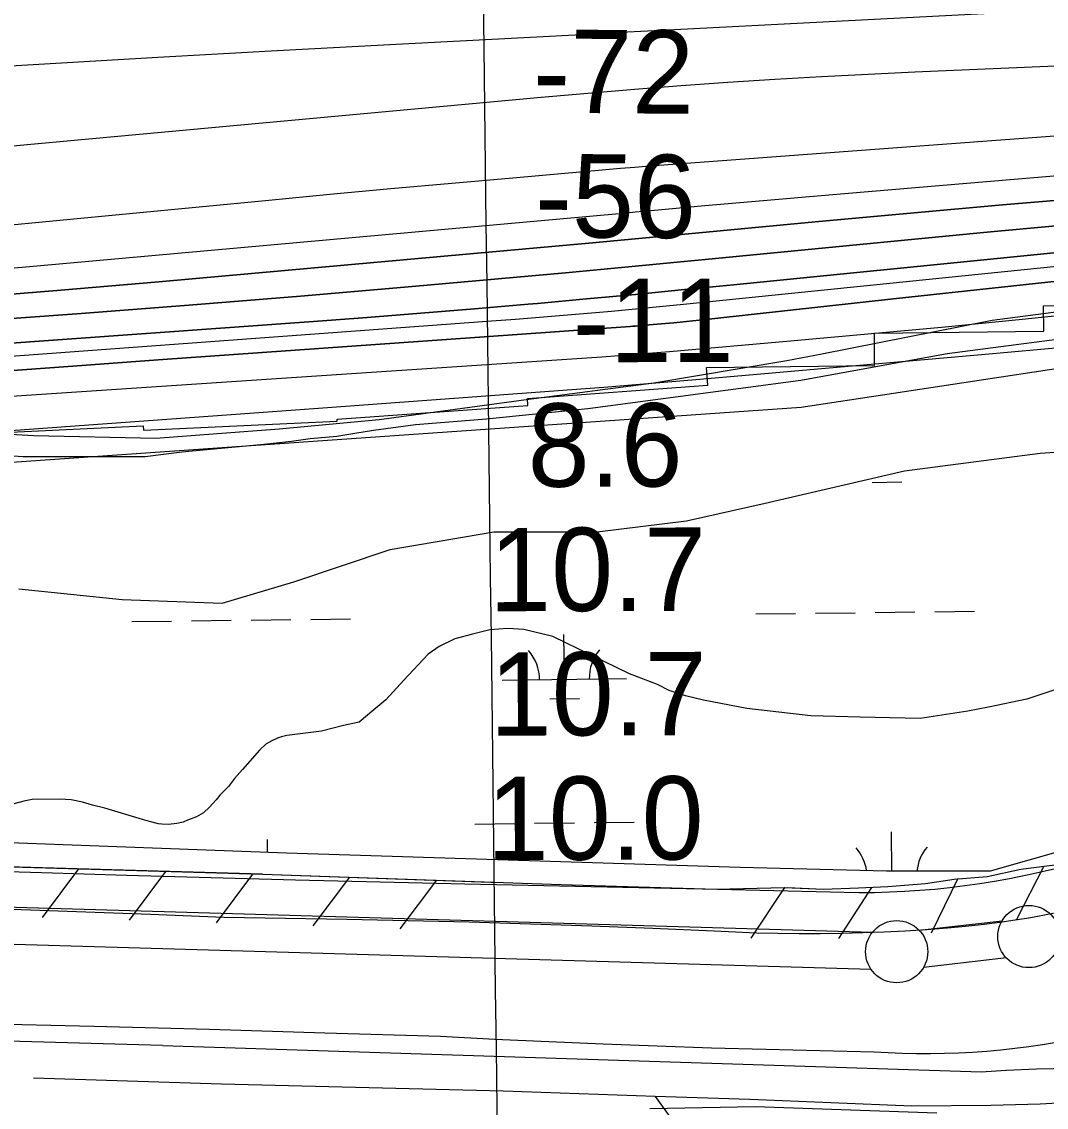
# Model space of a CAD drawing. Extents: x 3704301 to 3742427, y 506229 to 532009.
# Drawn here: x 3718668 to 3719492, y 518448 to 519321 of the extents above; entities that cross this region are included whole.
import ezdxf

# ---------------------------------------------------------------- set-up
doc = ezdxf.new("R2010")
doc.units = 0
for name, color, linetype in [('V-FLOD-BASE', 7, 'Continuous'), ('V-GRID-MAJR', 7, 'Continuous'), ('V-LEVE-TOET', 7, 'Continuous'), ('V-RIVR-EDGE', 7, 'Continuous'), ('V-RIVR-RANG', 7, 'Continuous'), ('V-ROAD-CNTR', 7, 'Continuous'), ('V-RRAP-FSHR', 7, 'Continuous'), ('V-RRAP-RVMT', 7, 'Continuous'), ('V-SITE-VEGE', 7, 'Continuous'), ('V-SURV-LINE', 7, 'Continuous'), ('V-TOPO-DPTH', 7, 'Continuous'), ('V-TOPO-MAJR', 7, 'Continuous'), ('V-TOPO-MINR', 7, 'Continuous'), ('V-TOPO-SHOR', 7, 'Continuous'), ('V-TOPO-WATR', 7, 'Continuous'), ('V-WETL-SWMP', 7, 'Continuous')]:
    doc.layers.add(name, color=color, linetype=linetype)

msp = doc.modelspace()

# ---------------------------------------------------------------- linework, layer by layer
at = {"layer": 'V-FLOD-BASE'}
msp.add_lwpolyline([(3719504.11, 518605.57), (3719491.77, 518603.07), (3719479.39, 518600.8), (3719466.96, 518598.76), (3719454.5, 518596.94), (3719442.02, 518595.35), (3719429.5, 518593.99), (3719412.49, 518592.48), (3719395.46, 518591.19), (3719378.42, 518590.11), (3719361.37, 518589.25), (3719344.31, 518588.6), (3719327.24, 518588.17), (3719310.16, 518587.95), (3719293.08, 518587.94), (3719276.01, 518588.15), (3719258.94, 518588.57), (3719241.88, 518589.21), (3719224.82, 518590.06), (3719175.59, 518592.16), (3719126.35, 518594.05), (3719077.1, 518595.73), (3719027.85, 518597.2), (3718978.58, 518598.46), (3718929.32, 518599.51), (3718880.05, 518600.35), (3718830.78, 518600.98), (3718771.41, 518603.39), (3718712.04, 518605.6), (3718652.66, 518607.61)], dxfattribs=at)
at = {"layer": 'V-GRID-MAJR'}
msp.add_spline([(3719130.79, 511775.21), (3719057.66, 517832.65), (3718984.49, 523893.16), (3718911.33, 529953.69), (3718911.29, 529956.76)], degree=3, dxfattribs=at)
at = {"layer": 'V-LEVE-TOET'}
for points in [[(3719505.13, 518641.52), (3719490.91, 518638.21), (3719476.65, 518635.12), (3719462.34, 518632.24), (3719450.38, 518630.05), (3719438.38, 518628.09), (3719426.34, 518626.37), (3719414.28, 518624.88), (3719402.18, 518623.63), (3719390.07, 518622.62), (3719377.94, 518621.84), (3719365.79, 518621.3), (3719353.64, 518621), (3719341.48, 518620.93), (3719329.32, 518621.11), (3719227.66, 518623.6), (3719125.99, 518625.82), (3719024.32, 518627.78), (3718956.25, 518629.32), (3718888.18, 518631), (3718820.11, 518632.82), (3718752.05, 518634.78), (3718683.99, 518636.88), (3718610.48, 518638.99)], [(3718633.06, 518515.85), (3718725.98, 518513.6), (3718818.88, 518511.13), (3718911.79, 518508.44), (3719004.68, 518505.54), (3719048.25, 518503.31), (3719091.83, 518501.27), (3719135.42, 518499.42), (3719179.01, 518497.77), (3719222.62, 518496.31), (3719266.22, 518495.05), (3719309.84, 518493.98), (3719353.46, 518493.11), (3719364.76, 518492.44), (3719376.08, 518491.98), (3719387.4, 518491.73), (3719398.72, 518491.7), (3719410.05, 518491.88), (3719421.36, 518492.27), (3719432.67, 518492.86), (3719443.97, 518493.67), (3719455.25, 518494.69), (3719466.51, 518495.92), (3719477.74, 518497.36), (3719488.94, 518499.01), (3719500.12, 518500.86)]]:
    msp.add_lwpolyline(points, dxfattribs=at)
at = {"layer": 'V-RIVR-EDGE'}
msp.add_lwpolyline([(3718613.12, 518992.21), (3718677.35, 518988.45), (3718775.8, 518986.4), (3718874.87, 518993.96), (3718955.33, 519001.57), (3719073.63, 519017.49), (3719176.32, 519031.04), (3719283.23, 519048.78), (3719311.45, 519054.12), (3719448.4, 519081.39), (3719507.85, 519089.05), (3719579.31, 519099.68), (3719683.19, 519106.03), (3719730.62, 519109.51), (3719758.24, 519110.04), (3719849.5, 519115.82), (3719962.37, 519120.95), (3720084.85, 519123.04), (3720165.91, 519129.45)], dxfattribs=at)
at = {"layer": 'V-ROAD-CNTR'}
for points in [[(3718780.98, 518498.22), (3718179.1, 518515.02), (3718151.75, 518517.62), (3718130.4, 518521.23), (3718088.05, 518529.99), (3717980.9, 518561.01), (3717958.85, 518565.95), (3717941.69, 518570.39), (3717923.51, 518575.15), (3717898.82, 518579.17), (3717869.02, 518585), (3717837.85, 518589.07), (3717807.08, 518590.8), (3717763.14, 518593.41), (3717074.31, 518630.34), (3717017.92, 518633.02), (3716960.94, 518633.92), (3716927.57, 518635.51), (3716890.7, 518634.15), (3716848.32, 518631.51), (3716792.89, 518627.14), (3716349.32, 518566.6)], [(3718780.98, 518498.22), (3719439.5, 518476.82), (3719459.76, 518478.2), (3719483.96, 518479.38), (3719497.61, 518479.51), (3719508.75, 518482.12), (3719520.69, 518484.95), (3719529.94, 518486.34), (3719540.83, 518488.96), (3719555.2, 518493.25), (3719641.91, 518528.4), (3719664.87, 518536.73), (3719678.8, 518542.61), (3719696, 518545.72), (3719715.73, 518546.86), (3719737.04, 518547.93), (3719767.36, 518551.18), (3719845.25, 518550.55), (3720856.93, 518524.63)]]:
    msp.add_lwpolyline(points, dxfattribs=at)
at = {"layer": 'V-RRAP-FSHR'}
for p, q in [((3719490, 518642.32), (3719467.61, 518598.93)), ((3718713.57, 518640.09), (3718684.41, 518600.92)), ((3718783.54, 518638.05), (3718754.38, 518598.88)), ((3718853.51, 518636.01), (3718824.35, 518596.84)), ((3718931.48, 518633.38), (3718902.12, 518594.36)), ((3719001.44, 518630.98), (3718972.08, 518591.96)), ((3719281.31, 518625.14), (3719254.24, 518584.5)), ((3719351.26, 518625.25), (3719324.69, 518584.28)), ((3719420.83, 518632.39), (3719399.36, 518588.53))]:
    msp.add_line(p, q, dxfattribs=at)
for points in [[(3713987.63, 518174.25), (3714448.77, 518564.74), (3714742.22, 518696.93), (3715881.89, 518753.27), (3716266.25, 518793.9), (3716843.09, 518890.74), (3717110.33, 518911.18), (3717741.27, 518924), (3718486.43, 518954.95), (3719294.78, 519011.25), (3719786.26, 519085.76), (3720431.33, 519110.59), (3720895.93, 519113.08), (3721218.47, 519068.37), (3721397.65, 519012.49), (3721721.32, 518965.44), (3721950.57, 518904.45), (3722606.87, 518712.52), (3722865.69, 518669.47), (3723100.48, 518674.85), (3723533.38, 518647.14), (3724154.01, 518572.99), (3724673.75, 518469.16)], [(3718861.52, 518635.77), (3718367.7, 518650.18), (3718265.84, 518650.62), (3718237.82, 518650.14), (3718217.37, 518650.6), (3718200.31, 518651.67), (3718184.58, 518653.45), (3718163.8, 518658.07), (3718142.73, 518661.93), (3718022.93, 518693.81), (3717983.32, 518705.81), (3717948.34, 518717.06), (3717925.8, 518722.8), (3717893.09, 518732.65), (3717875.83, 518735.03), (3717849.56, 518738.61), (3717822.3, 518743.28), (3717746.78, 518757.76)], [(3719283.72, 518625.05), (3719312.71, 518623.88), (3719340.83, 518624.88), (3719364.49, 518625.83), (3719394.78, 518628.3), (3719417.78, 518631.91), (3719444.38, 518634.03), (3719471.42, 518639.8), (3719502.85, 518644.05), (3719530.7, 518650.31), (3719559.2, 518659.16), (3719580.64, 518663.11), (3719627.37, 518680), (3719666.55, 518692.79), (3719687.92, 518695.17), (3719712.78, 518699.21), (3719734.68, 518701.82), (3719755.2, 518702.93), (3719773.84, 518703.34), (3719819.33, 518705.33), (3719891.74, 518705.49), (3719938.7, 518703.82)], [(3718410.89, 518648.92), (3718861.52, 518635.77)], [(3718861.52, 518635.77), (3719101.7, 518627.55), (3719226.4, 518623.87), (3719281.29, 518625.14), (3719312.71, 518623.88), (3719340.83, 518624.88), (3719364.49, 518625.83), (3719394.78, 518628.3), (3719417.78, 518631.91), (3719444.38, 518634.03), (3719471.42, 518639.8), (3719502.85, 518644.05)], [(3718861.52, 518635.77), (3719052.8, 518629.22)]]:
    msp.add_lwpolyline(points, dxfattribs=at)
at = {"layer": 'V-RRAP-RVMT'}
msp.add_lwpolyline([(3718624.91, 518989.72), (3718765.65, 518996.22), (3718765.79, 518992.89), (3718921.71, 519000.11), (3718921.66, 519001.68), (3719074.94, 519012.79), (3719074.61, 519018.44), (3719219.56, 519028.94), (3719218.65, 519043.21), (3719353.86, 519044.77), (3719353.69, 519070.97), (3719489.85, 519072.45), (3719489.66, 519092.76), (3719629.3, 519094.36), (3719629.21, 519106.55), (3719771.05, 519108.2), (3719770.83, 519126.15), (3719891.78, 519127.59), (3719891.81, 519125.3), (3720047.98, 519127.07), (3720047.89, 519131.44), (3720183.27, 519132.94)], dxfattribs=at)
at = {"layer": 'V-SITE-VEGE'}
for points in [[(3718617.46, 518975.48), (3718668.67, 518971.7), (3718767.13, 518971.67), (3718796.75, 518975.42), (3718859.86, 518981.39), (3718872.72, 518982.77), (3718884.84, 518984.15), (3718899.8, 518986.24), (3718921.33, 518988.13), (3718935.7, 518990.54), (3718950.81, 518992.93), (3718984.47, 518997.54), (3719041.73, 519001.93), (3719123.24, 519010.27), (3719294.38, 519033), (3719412.17, 519054.45), (3719543.82, 519071.73)], [(3719500.4, 518784.7), (3719476.3, 518776.69), (3719445.34, 518770.12), (3719428.83, 518766.84), (3719390.33, 518761.03), (3719342.29, 518762.17), (3719302.48, 518763.23), (3719251.05, 518769.21), (3719216.1, 518775.73), (3719201.71, 518779.29), (3719188.71, 518783.54), (3719179.14, 518788.43), (3719156.57, 518796.89), (3719095.07, 518826.99), (3719071.78, 518832.7), (3719058.74, 518833.51), (3719044.31, 518832.28), (3719030.55, 518828.97), (3719016.1, 518824.99), (3719003.68, 518818.93), (3718994.7, 518812.84), (3718975.27, 518791.74), (3718960.71, 518776.09), (3718951.02, 518767.94), (3718939.32, 518758.02), (3718926.59, 518755.3), (3718908.92, 518750.84), (3718881.1, 518747.37), (3718876.9, 518746.36), (3718873.46, 518745.2), (3718868.95, 518743), (3718864.15, 518740.36), (3718859.17, 518735.47), (3718845.43, 518720.06), (3718839.08, 518712.8), (3718834.09, 518706.43), (3718827.3, 518699.32), (3718824.13, 518695.61), (3718818.84, 518689.69), (3718814.17, 518685.25), (3718808.46, 518681.87), (3718801.26, 518679.25), (3718797.81, 518677.64), (3718792.72, 518676.49), (3718785.84, 518675.81), (3718780.46, 518676.01), (3718777.93, 518676.48), (3718770.77, 518678.19), (3718764.96, 518679.74), (3718734.72, 518688.84), (3718724.73, 518691.33), (3718716.83, 518693.64), (3718707.74, 518695.67), (3718698.63, 518696.21), (3718676.37, 518695.82), (3718669.48, 518694.69), (3718658.54, 518691.66)], [(3719172.94, 518447.45), (3719257.75, 518449.18), (3719403.8, 518443.99)]]:
    msp.add_lwpolyline(points, dxfattribs=at)
at = {"layer": 'V-SURV-LINE'}
for points in [[(3718203.02, 518622.79), (3719352.04, 518589.13)], [(3719389.71, 518590.72), (3719456.37, 518598.34)], [(3719351.14, 518559.14), (3718202.12, 518592.8)], [(3719459.79, 518568.54), (3719393.14, 518560.91)]]:
    msp.add_lwpolyline(points, dxfattribs=at)
for centre in [(3719477.93, 518585.71), (3719371.57, 518573.55)]:
    msp.add_circle(centre, 25, dxfattribs=at)
at = {"layer": 'V-TOPO-DPTH'}
for points in [[(3720182.74, 519226.67), (3720067.37, 519221.27), (3720039.13, 519219.8), (3720010.9, 519218.16), (3719982.68, 519216.23), (3719954.48, 519214.12), (3719604.36, 519186.22), (3719530.47, 519180.17), (3719456.59, 519173.91), (3719382.75, 519167.33), (3719308.92, 519160.54), (3719195.53, 519149.87), (3719178.41, 519148.27), (3719161.29, 519146.69), (3719144.17, 519145.12), (3719127.05, 519143.57), (3718778.09, 519112.24), (3718699.3, 519105.46), (3718620.49, 519099.07)], [(3720182.74, 519226.67), (3720067.37, 519221.27), (3720039.13, 519219.8), (3720010.9, 519218.16), (3719982.68, 519216.23), (3719954.48, 519214.12), (3719604.36, 519186.22), (3719530.47, 519180.17), (3719456.59, 519173.91), (3719382.75, 519167.33), (3719308.92, 519160.54), (3719195.53, 519149.87), (3719178.41, 519148.27), (3719161.29, 519146.69), (3719144.17, 519145.12), (3719127.05, 519143.57), (3718778.09, 519112.24), (3718699.3, 519105.46), (3718620.49, 519099.07)], [(3720347.73, 519212.76), (3720047.64, 519200.25), (3720029.32, 519199.39), (3720011.02, 519198.41), (3719992.72, 519197.25), (3719974.43, 519195.97), (3719822.85, 519184.59), (3719728.81, 519177.21), (3719634.8, 519169.43), (3719540.84, 519161.03), (3719446.92, 519152.23), (3719217.66, 519129.97), (3719189.53, 519127.27), (3719161.39, 519124.62), (3719133.25, 519122.02), (3719105.11, 519119.47), (3718981.81, 519108.44), (3718891.99, 519100.68), (3718802.15, 519093.3), (3718712.25, 519086.48), (3718622.33, 519080.03)], [(3718622.33, 519080.03), (3718712.25, 519086.48), (3718802.15, 519093.3), (3718891.99, 519100.68), (3718981.81, 519108.44), (3719105.11, 519119.47), (3719133.25, 519122.02), (3719161.39, 519124.62), (3719189.53, 519127.27), (3719217.66, 519129.97), (3719446.92, 519152.23), (3719540.84, 519161.03), (3719634.8, 519169.43), (3719728.81, 519177.21), (3719822.85, 519184.59), (3719974.43, 519195.97), (3719992.72, 519197.25), (3720011.02, 519198.41), (3720029.32, 519199.39), (3720047.64, 519200.25), (3720347.73, 519212.76)], [(3720614.17, 519202.87), (3720029.9, 519181.53), (3720020.51, 519181.14), (3720011.12, 519180.69), (3720001.74, 519180.14), (3719992.37, 519179.52), (3719909.74, 519173.71), (3719859.06, 519169.92), (3719808.42, 519165.83), (3719757.81, 519161.3), (3719707.23, 519156.46), (3719240.29, 519109.74), (3719200.89, 519105.87), (3719161.49, 519102.07), (3719122.07, 519098.41), (3719082.65, 519094.83), (3719075.21, 519094.17), (3719032.05, 519090.44), (3718988.88, 519086.85), (3718945.7, 519083.49), (3718902.5, 519080.28), (3718375.16, 519042.43)], [(3718375.16, 519042.43), (3718902.5, 519080.28), (3718945.7, 519083.49), (3718988.88, 519086.85), (3719032.05, 519090.44), (3719075.21, 519094.17), (3719082.65, 519094.83), (3719122.07, 519098.41), (3719161.49, 519102.07), (3719200.89, 519105.87), (3719240.29, 519109.74), (3719707.23, 519156.46), (3719757.81, 519161.3), (3719808.42, 519165.83), (3719859.06, 519169.92), (3719909.74, 519173.71), (3719992.37, 519179.52), (3720001.74, 519180.14), (3720011.12, 519180.69), (3720020.51, 519181.14), (3720029.9, 519181.53), (3720614.17, 519202.87)], [(3718327.84, 519016.7), (3718705.35, 519044.09), (3718781.39, 519049.59), (3718857.44, 519055.05), (3718933.48, 519060.46), (3719009.53, 519065.84), (3719157.15, 519076.23), (3719159.39, 519076.39), (3719161.63, 519076.56), (3719163.87, 519076.74), (3719166.1, 519076.93), (3719182.05, 519078.33), (3719192.25, 519079.26), (3719202.46, 519080.23), (3719212.65, 519081.27), (3719222.84, 519082.35), (3719371.42, 519098.63), (3719455.91, 519107.83), (3719540.4, 519116.93)], [(3719540.4, 519116.93), (3719455.91, 519107.83), (3719371.42, 519098.63), (3719222.84, 519082.35), (3719212.65, 519081.27), (3719202.46, 519080.23), (3719192.25, 519079.26), (3719182.05, 519078.33), (3719166.1, 519076.93), (3719163.87, 519076.74), (3719161.63, 519076.56), (3719159.39, 519076.39), (3719157.15, 519076.23), (3719009.53, 519065.84), (3718933.48, 519060.46), (3718857.44, 519055.05), (3718781.39, 519049.59), (3718705.35, 519044.09), (3718327.84, 519016.7)], [(3718603.58, 518988.68), (3718703.35, 518995.73), (3718803.12, 519002.94), (3718902.88, 519010.24), (3719110.37, 519025.59), (3719136.11, 519027.55), (3719161.84, 519029.58), (3719187.57, 519031.71), (3719213.29, 519033.92), (3719439.81, 519053.82), (3719535.12, 519062.21), (3719630.42, 519070.63), (3719725.72, 519079.08), (3719821.03, 519087.56), (3719969.3, 519100.78), (3719990.47, 519102.55), (3720011.65, 519104.17), (3720032.85, 519105.57), (3720054.06, 519106.81), (3720227.73, 519116.07)]]:
    msp.add_lwpolyline(points, dxfattribs=at)
at = {"layer": 'V-TOPO-MAJR'}
msp.add_lwpolyline([(3718512.72, 519109.91), (3719148.5, 519167.14), (3719154.85, 519167.72), (3719161.19, 519168.29), (3719167.54, 519168.87), (3719173.88, 519169.44), (3719217.33, 519173.4), (3719245.4, 519175.93), (3719273.48, 519178.42), (3719301.56, 519180.86), (3719329.64, 519183.25), (3719932.49, 519233.97), (3719971.62, 519237.08), (3720010.76, 519239.93), (3720049.94, 519242.41), (3720089.12, 519244.63), (3720092.47, 519244.81), (3720133.35, 519246.6)], dxfattribs=at)
at = {"layer": 'V-TOPO-MINR'}
for points in [[(3718586, 519281.53), (3718681.73, 519287.23), (3718777.46, 519292.77), (3718873.21, 519298.09), (3718968.97, 519303.25), (3719128.22, 519311.65), (3719144.36, 519312.5), (3719160.51, 519313.35), (3719176.65, 519314.19), (3719192.79, 519315.03), (3719851.62, 519349.24)], [(3718538.13, 519210.27), (3719085.72, 519260.57), (3719123.23, 519263.88), (3719160.76, 519267.02), (3719198.31, 519269.88), (3719235.87, 519272.57), (3719273.46, 519274.98), (3719311.05, 519277.2), (3719348.66, 519279.14), (3719386.28, 519280.88), (3719964.86, 519305.57), (3719987.57, 519306.45), (3720010.28, 519307.21), (3720033, 519307.79), (3720055.73, 519308.26), (3720416.68, 519314.19)], [(3718361.96, 519129.55), (3718866.55, 519177.85), (3718915.61, 519182.48), (3718964.68, 519187.04), (3719013.76, 519191.49), (3719062.84, 519195.86), (3719137.66, 519202.43), (3719149.34, 519203.43), (3719161.03, 519204.4), (3719172.71, 519205.32), (3719184.41, 519206.22), (3719925.15, 519261.21), (3719939.37, 519262.2), (3719953.59, 519263.1), (3719967.83, 519263.87), (3719982.07, 519264.56), (3720006.82, 519265.63), (3720008.69, 519265.7), (3720010.56, 519265.77), (3720012.42, 519265.82), (3720014.29, 519265.87), (3720207.98, 519270.29)], [(3718620.49, 519099.07), (3718699.3, 519105.46), (3718778.09, 519112.24), (3719127.05, 519143.57), (3719144.17, 519145.12), (3719161.29, 519146.69), (3719178.41, 519148.27), (3719195.53, 519149.87), (3719308.92, 519160.54), (3719382.75, 519167.33), (3719456.59, 519173.91), (3719530.47, 519180.17), (3719604.36, 519186.22), (3719954.48, 519214.12), (3719982.68, 519216.23), (3720010.9, 519218.16), (3720039.13, 519219.8), (3720067.37, 519221.27), (3720182.74, 519226.67)], [(3718622.33, 519080.03), (3718712.25, 519086.48), (3718802.15, 519093.3), (3718891.99, 519100.68), (3718981.81, 519108.44), (3719105.11, 519119.47), (3719133.25, 519122.02), (3719161.39, 519124.62), (3719189.53, 519127.27), (3719217.66, 519129.97), (3719446.92, 519152.23), (3719540.84, 519161.03), (3719634.8, 519169.43), (3719728.81, 519177.21), (3719822.85, 519184.59), (3719974.43, 519195.97), (3719992.72, 519197.25), (3720011.02, 519198.41), (3720029.32, 519199.39), (3720047.64, 519200.25), (3720347.73, 519212.76)], [(3718375.16, 519042.43), (3718902.5, 519080.28), (3718945.7, 519083.49), (3718988.88, 519086.85), (3719032.05, 519090.44), (3719075.21, 519094.17), (3719082.65, 519094.83), (3719122.07, 519098.41), (3719161.49, 519102.07), (3719200.89, 519105.87), (3719240.29, 519109.74), (3719707.23, 519156.46), (3719757.81, 519161.3), (3719808.42, 519165.83), (3719859.06, 519169.92), (3719909.74, 519173.71), (3719992.37, 519179.52), (3720001.74, 519180.14), (3720011.12, 519180.69), (3720020.51, 519181.14), (3720029.9, 519181.53), (3720614.17, 519202.87)], [(3718367.12, 519030.95), (3719045.59, 519080.64), (3719064.93, 519082.1), (3719084.27, 519083.62), (3719103.6, 519085.23), (3719122.92, 519086.91), (3719142.24, 519088.66), (3719161.55, 519090.46), (3719180.86, 519092.34), (3719200.16, 519094.26), (3719834.95, 519158.72), (3719864.28, 519161.55), (3719893.62, 519164.19), (3719922.99, 519166.53), (3719952.37, 519168.67), (3720000.58, 519171.94), (3720005.88, 519172.28), (3720011.17, 519172.57), (3720016.47, 519172.81), (3720021.78, 519173.02), (3720746.61, 519197.61)], [(3718482.27, 519008.28), (3719134.53, 519051.94), (3719148.13, 519052.89), (3719161.73, 519053.9), (3719175.32, 519054.99), (3719188.91, 519056.13), (3719286.12, 519064.62), (3719348.3, 519070.21), (3719410.46, 519076.02), (3719472.58, 519082.15), (3719534.68, 519088.5), (3719935.38, 519130.52), (3719973.41, 519134.27), (3720011.46, 519137.7), (3720049.56, 519140.65), (3720087.68, 519143.29), (3720093.95, 519143.69), (3720135.24, 519145.83)], [(3718327.84, 519016.7), (3718705.35, 519044.09), (3718781.39, 519049.59), (3718857.44, 519055.05), (3718933.48, 519060.46), (3719009.53, 519065.84), (3719157.15, 519076.23), (3719159.39, 519076.39), (3719161.63, 519076.56), (3719163.87, 519076.74), (3719166.1, 519076.93), (3719182.05, 519078.33), (3719192.25, 519079.26), (3719202.46, 519080.23), (3719212.65, 519081.27), (3719222.84, 519082.35), (3719371.42, 519098.63), (3719455.91, 519107.83), (3719540.4, 519116.93)]]:
    msp.add_lwpolyline(points, dxfattribs=at)
at = {"layer": 'V-TOPO-SHOR'}
for points in [[(3719501.24, 518451.7), (3719487, 518450.94), (3719447.4, 518449.87), (3719383.74, 518449.45), (3719253.46, 518454.74), (3719177.4, 518457.25), (3719055.15, 518461.29), (3718828.57, 518466.95), (3718677.26, 518471.96)], [(3719177.4, 518457.25), (3719193.36, 518434.92), (3719229.37, 518401.89), (3719338.76, 518280.43), (3719533.16, 518095.95), (3719778.12, 517855.4), (3719900.24, 517744.46)]]:
    msp.add_lwpolyline(points, dxfattribs=at)
at = {"layer": 'V-TOPO-WATR'}
msp.add_lwpolyline([(3718603.58, 518988.68), (3718703.35, 518995.73), (3718803.12, 519002.94), (3718902.88, 519010.24), (3719110.37, 519025.59), (3719136.11, 519027.55), (3719161.84, 519029.58), (3719187.57, 519031.71), (3719213.29, 519033.92), (3719439.81, 519053.82), (3719535.12, 519062.21), (3719630.42, 519070.63), (3719725.72, 519079.08), (3719821.03, 519087.56), (3719969.3, 519100.78), (3719990.47, 519102.55), (3720011.65, 519104.17), (3720032.85, 519105.57), (3720054.06, 519106.81), (3720227.73, 519116.07)], dxfattribs=at)
at = {"layer": 'V-WETL-SWMP'}
for p, q in [((3719351.86, 518950.91), (3719375.85, 518951.21)), ((3719258.3, 518845.12), (3719290.29, 518845.51)), ((3719306.29, 518845.71), (3719338.29, 518846.1)), ((3719354.29, 518846.3), (3719386.29, 518846.69)), ((3719402.29, 518846.88), (3719434.28, 518847.27)), ((3718756.43, 518838.99), (3718788.42, 518839.38)), ((3718804.42, 518839.58), (3718836.42, 518839.97)), ((3718852.42, 518840.16), (3718884.42, 518840.55)), ((3718900.42, 518840.75), (3718932.41, 518841.14)), ((3719104.34, 518792.5), (3719103.9, 518828.49)), ((3719054.34, 518791.88), (3719154.33, 518793.11)), ((3719092.53, 518776.92), (3719116.52, 518777.21)), ((3719032.34, 518676.18), (3719064.34, 518676.57)), ((3719080.34, 518676.76), (3719112.34, 518677.15)), ((3719128.34, 518677.35), (3719160.33, 518677.74)), ((3719367.68, 518638.32), (3719367.29, 518669.84)), ((3718865.55, 518653.26), (3718865.42, 518663.71))]:
    msp.add_line(p, q, dxfattribs=at)
for points in [[(3718665.44, 518865.27), (3718748.74, 518856.65), (3718829.18, 518853.77), (3718886.63, 518871.01), (3718964.2, 518896.86), (3719047.51, 518911.23), (3719130.81, 518911.23), (3719202.63, 518919.85), (3719265.83, 518934.21), (3719377.87, 518960.07), (3719420.96, 518965.81), (3719487.03, 518974.43), (3719573.21, 518980.17)], [(3720187.97, 518779.08), (3720119.03, 518715.88), (3720084.56, 518707.27), (3720004.12, 518715.88), (3719917.94, 518718.76), (3719803.03, 518718.76), (3719728.34, 518713.01), (3719639.29, 518692.9), (3719558.85, 518672.79), (3719507.14, 518655.56), (3719446.81, 518638.32), (3719363.5, 518638.32), (3719245.72, 518641.19), (3718880.89, 518652.68), (3718651.07, 518661.3)]]:
    msp.add_lwpolyline(points, dxfattribs=at)
for centre, start, end in [((3719159.57, 518793.65), 139.9282, 181.47186), ((3719049.09, 518792.3), 359.9282, 41.47186), ((3719312.49, 518633.64), 8.2784, 41.47186), ((3719422.96, 518634.99), 139.9282, 174.57652)]:
    msp.add_arc(centre, 35.25, start, end, dxfattribs=at)

# ---------------------------------------------------------------- texts
at = {"layer": 'V-RIVR-RANG'}
for s, rotation, p in [('-72', 359.58517, (3719078.91, 519248.12)), ('-56', 359.58517, (3719080.44, 519148.11)), ('-11', 0.12833, (3719111.04, 519047.42)), ('8.6', 0.12833, (3719074.85, 518947.34)), ('10.7', 0.12833, (3719043.94, 518847.27)), ('10.7', 0.12833, (3719044.41, 518747.27)), ('10.0', 0.12833, (3719041.99, 518647.26))]:
    msp.add_text(s, height=67, rotation=rotation, dxfattribs=at).set_placement(p)

doc.saveas('drawing.dxf')
